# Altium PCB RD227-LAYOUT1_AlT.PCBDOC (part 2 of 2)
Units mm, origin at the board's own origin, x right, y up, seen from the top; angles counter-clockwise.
Board outline 90 x 40 mm, 4 copper layers (TOP, Mid-Layer 1, Mid-Layer 2, BOTTOM), stack 0.711 mm thick; 157 components, 70 nets, 392 pads, 454 vias.
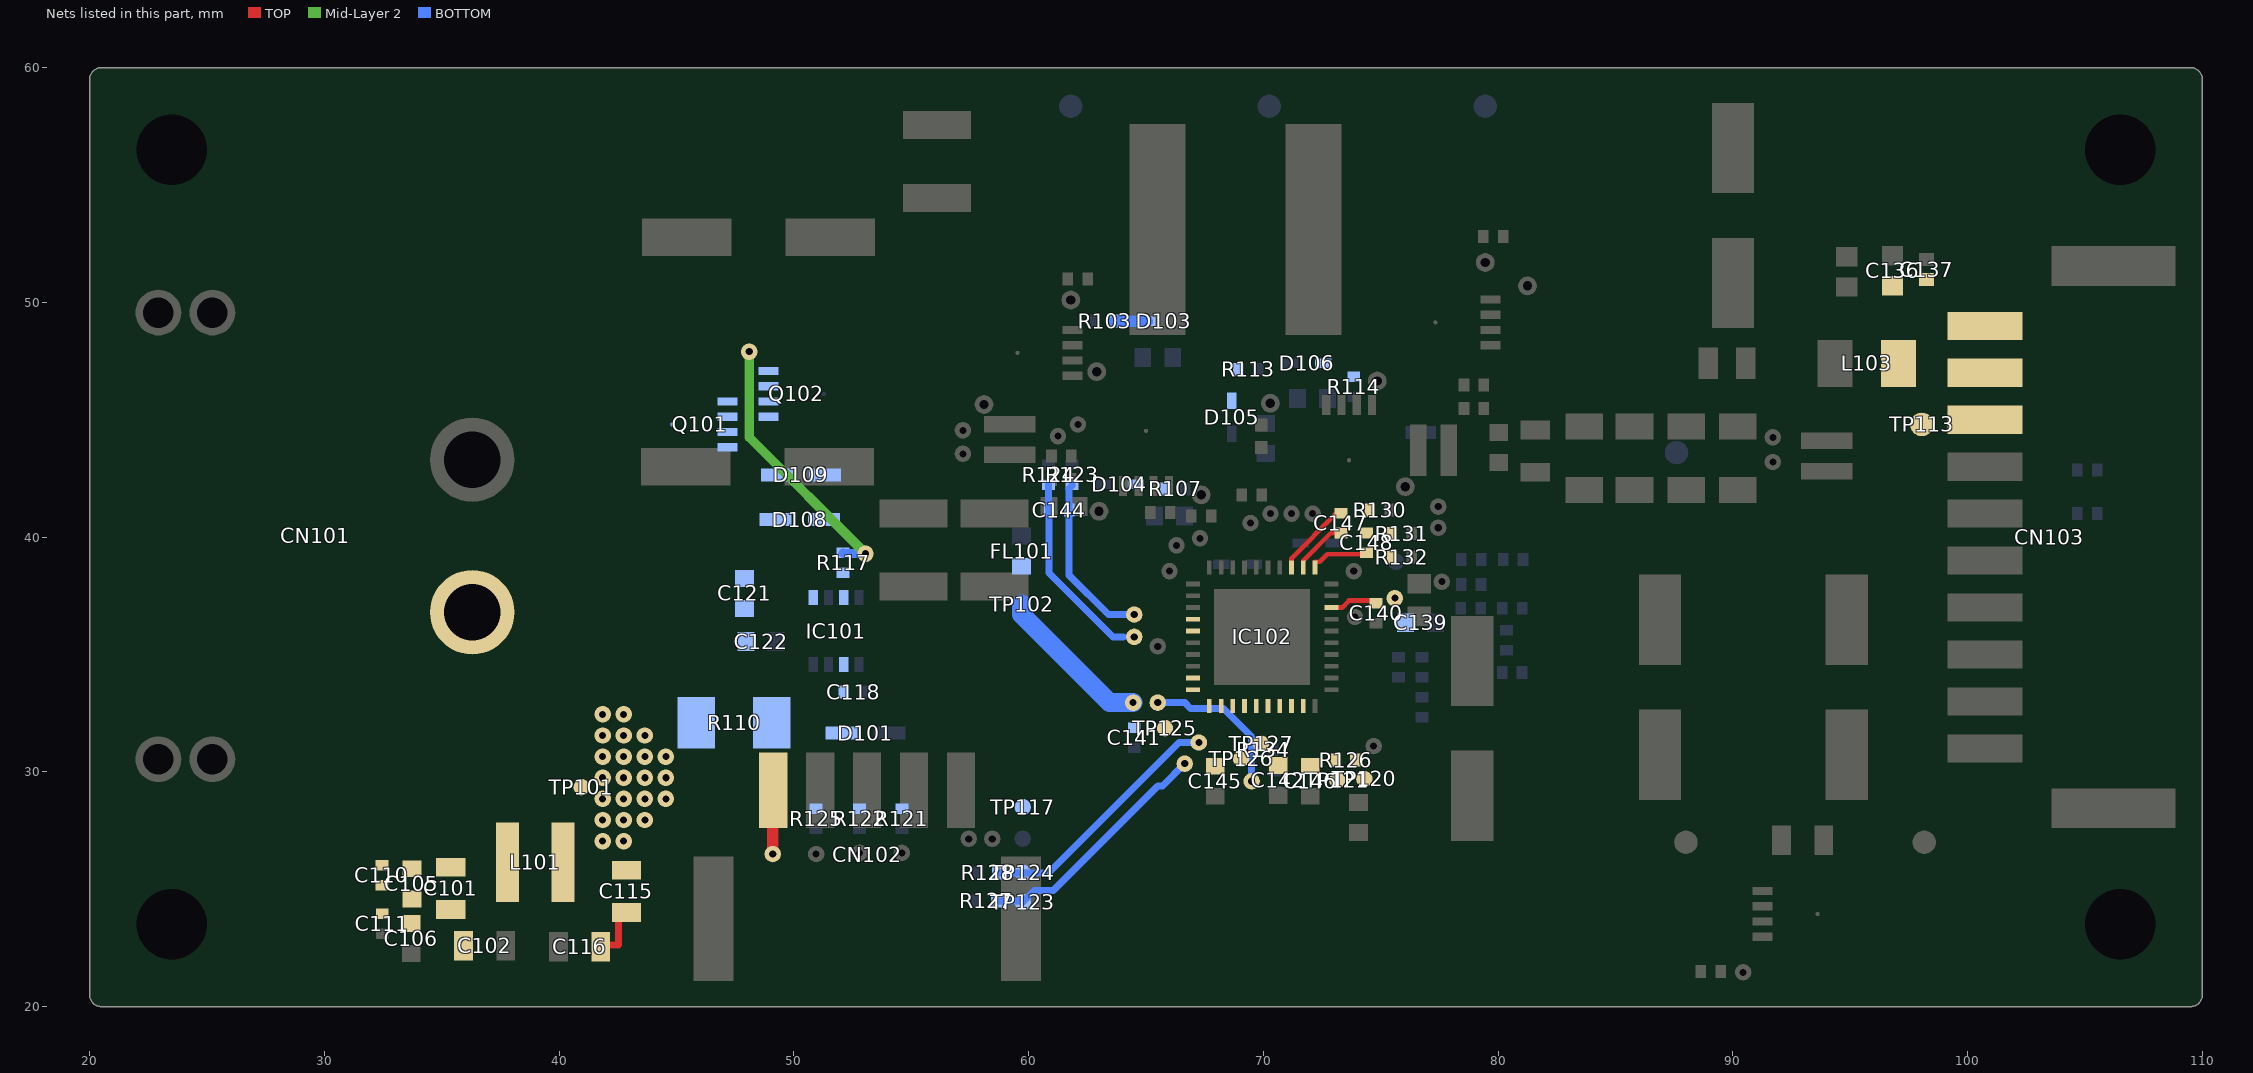
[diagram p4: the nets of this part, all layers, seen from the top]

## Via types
v1: diameter 0.7, hole 0.3, TOP to BOTTOM, 414 vias
v2: diameter 0.8, hole 0.4, TOP to BOTTOM, 40 vias

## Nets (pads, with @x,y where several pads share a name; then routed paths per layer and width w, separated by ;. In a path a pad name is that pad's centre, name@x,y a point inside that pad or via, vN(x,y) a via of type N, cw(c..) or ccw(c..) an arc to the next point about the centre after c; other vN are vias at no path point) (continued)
SIG319: C147.1 C148.2 IC102.32 R131.2 | length 1.9
  TOP w0.2: IC102.32@71.7,38.948 71.7,39 72.875,40.175 C147.1@73.1,40.175
SIG324: C148.1 IC102.31 R132.2 | length 2.5
  TOP w0.2: IC102.31@72.2,38.948 72.398,38.948 72.725,39.275 C148.1@74.575,39.275
SIG328: C147.2 IC102.33 R130.2 | length 3.1
  TOP w0.2: IC102.33@71.2,38.8 71.2,39.1 73.113,41.013 C147.2@73.175,40.95
SIG335: C144.1 IC102.5 pad.@64.5,35.75 R124.1 | length 8.5
  BOTTOM w0.2: 64.05,35.75 pad.@64.5,35.75
  BOTTOM w0.3: R124.1@60.85,42.225 60.85,41.175 C144.1@60.875,41.15 60.875,38.475 63.6,35.75 64.05,35.75
SIG337: C144.2 IC102.4 pad.@64.5,36.7 R123.1 | length 7.4
  BOTTOM w0.3: R123.1@61.85,42.225 61.84,42.235 61.84,42.18 61.725,42.065 C144.2@61.725,41.15 61.725,38.375 63.4,36.7 pad.@64.5,36.7
SIG341: IC102.10 TP125.1
SIG344: IC102.19 R126.1 TP120.1
SIG345: IC102.18 R126.2 TP121.1
SIG346: C145.1 IC102.13
SIG347: C146.1 IC102.17
SIG349: IC102.14 TP126.1
SIG350: IC102.15 TP127.1
SIG369: IC102.11 pad.@66.65,30.35 R127.1 TP123.1 | length 10.4
  BOTTOM w0.3: R127.1@58.675,24.5 59.7,24.5 TP123.1@59.75,24.45 60.25,24.95 61.05,24.95 65.503,29.403 65.703,29.403 pad.@66.65,30.35
SIG370: IC102.12 pad.@67.25,31.25 R128.1 TP124.1 | length 10.9
  BOTTOM w0.3: R128.1@58.675,25.7 TP124.1@59.75,25.7 60.85,25.7 66.4,31.25 pad.@67.25,31.25
SIG422: C118.2 D101.C IC101.6 R110.1
SIG424: D103.A R103.2 | length 1.4
  BOTTOM w0.5: R103.2@63.675,49.2 D103.A@65.05,49.2
SIG425: D104.A R107.2
SIG426: D109.A Q101.1 Q101.2 Q101.3 Q102.1 Q102.2 Q102.3
SIG427: C101.1 C102.2
SIG428: C105.1 C106.2
SIG429: C110.1 C111.2
SIG432: C121.1 C122.2
SIG434: D105.A R113.2
SIG435: D106.A R114.2
SIG439: C115.1 C116.2 | length 2.1
  TOP w0.3: C116.2@41.802,22.63 42.531,22.63 C115.1@42.531,23.955
SIG446: IC101.3 R117.1
SIG449: D108.C D109.C
SIG450: D108.A Q101.4 Q102.4 R117.2 | length 11.6
  Mid-Layer 2 w0.4: v1(48.1,47.9) 48.1,44.25 v1(53.05,39.3)
  BOTTOM w0.4: R117.2@52.1,39.325 52.125,39.3 v1(53.05,39.3) v1@53.075,39.3
VBAT: C139.2 C140.2 FL101.2 IC102.28 TP102.1 | length 9
  TOP w0.2: IC102.28@72.898,37 73.35,37 73.65,37.3 C140.2@74.925,37.3
  BOTTOM w0.3: v1(75.6,37.4) v1@75.646,37.446
  BOTTOM w0.8: TP102.1@59.7,37.15 59.7,36.7 63.45,32.95 v1(64.45,32.95)
VBUS: C136.2 C137.2 CN103.8 CN103.9 CN103.10 L103.2 TP113.1
VDD: C141.2 C142.1 CN102.1 IC102.9 IC102.16 pad.@49.1,26.5 pad.@65.5,32.95 pad.@69.5,29.6 R121.1 R122.1 R125.1 R134.1 TP117.1 | length 9.2
  TOP w0.5: pad.@49.1,26.5 CN102.1@49.1,29.2
  BOTTOM w0.3: pad.@65.5,32.95 66.65,32.95 66.9,32.7 68.3,32.7 69.5,31.5 pad.@69.5,29.6
VIN: C101.2 C105.2 C110.2 CN101.1 L101.1
VIN2: C115.2 C121.2 IC101.1 L101.2 Q101.5 R110.2 TP101.1
  other v1: 41.85,27.05 42.75,27.05 41.85,27.95 42.75,27.95 43.65,27.95 41.85,28.85 42.75,28.85 43.65,28.85 44.55,28.85 41.85,29.75 42.75,29.75 43.65,29.75 44.55,29.75 41.85,30.65 42.75,30.65 43.65,30.65 44.55,30.65 41.85,31.55 42.75,31.55 43.65,31.55 41.85,32.45 42.75,32.45
pads on no net: CAM10. CAM11. CAM12. CAM13. IC101.4 IC101.7 IC101.8

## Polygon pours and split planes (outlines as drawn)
DL1_Q on TOP "TOP1" (solid, pour order 71): 20 vertices, not listed, extent 65.8,40.85 67.3,42.55
DH1 on TOP "TOP2" (solid, pour order 72): 67.65,38.4 cw(c67.65,38.45) 67.6,38.45 67.6,39.2 66.965,39.835 cw(c67,39.871) 66.95,39.871 66.95,40.079 cw(c67,40.079) 66.965,40.115 67.135,40.285 cw(c67.171,40.25) 67.171,40.3 67.429,40.3 cw(c67.429,40.25) 67.465,40.285 67.785,39.965 cw(c67.75,39.929) 67.8,39.929 67.8,38.45 cw(c67.75,38.45) 67.75,38.4
SIG319 on TOP "TOP3" (solid, pour order 73): 75.271,39.85 cw(c75.271,39.9) 75.235,39.865 75.15,39.95 73.1,39.95 cw(c73.1,40) 73.05,40 73.05,40.35 cw(c73.1,40.35) 73.1,40.4 75.55,40.4 cw(c75.55,40.35) 75.6,40.35 75.6,39.9 cw(c75.55,39.9) 75.55,39.85
SIG318 on TOP "TOP4" (solid, pour order 74): 72.75,37.9 cw(c72.75,37.95) 72.7,37.95 72.7,38.05 cw(c72.75,38.05) 72.75,38.1 73,38.1 73.435,38.535 cw(c73.471,38.5) 73.471,38.55 74,38.55 cw(c74,38.5) 74.05,38.5 74.05,38.25 cw(c74,38.25) 74,38.2 73.5,38.2 73.215,37.915 cw(c73.179,37.95) 73.179,37.9
SIG310 on TOP "TOP5" (solid, pour order 75): 73.15,36.4 cw(c73.15,36.45) 73.1,36.45 73.1,36.55 cw(c73.15,36.55) 73.15,36.6 73.4,36.6 73.685,36.885 cw(c73.721,36.85) 73.721,36.9 73.9,36.9 cw(c73.9,36.85) 73.95,36.85 73.95,36.45 cw(c73.9,36.45) 73.9,36.4
SIG324 on TOP "TOP6" (solid, pour order 76): 75.071,38.9 cw(c75.071,38.95) 75.035,38.915 74.85,39.1 74.2,39.1 cw(c74.2,39.15) 74.15,39.15 74.15,39.5 cw(c74.2,39.5) 74.2,39.55 75.079,39.55 cw(c75.079,39.5) 75.115,39.535 75.25,39.4 75.45,39.4 cw(c75.45,39.35) 75.5,39.35 75.5,38.95 cw(c75.45,38.95) 75.45,38.9
SIG328 on TOP "TOP7" (solid, pour order 77): 73,40.8 cw(c73,40.85) 72.95,40.85 72.95,41.2 cw(c73,41.2) 73,41.25 73.7,41.25 73.835,41.385 cw(c73.871,41.35) 73.871,41.4 74.6,41.4 cw(c74.6,41.35) 74.65,41.35 74.65,40.95 cw(c74.6,40.95) 74.6,40.9 74.2,40.9 74.115,40.815 cw(c74.079,40.85) 74.079,40.8
CSN2 on TOP "TOP8" (solid, pour order 78): 76.15,38.9 cw(c76.15,38.95) 76.1,38.95 76.1,39.4 cw(c76.15,39.4) 76.15,39.45 76.65,39.45 77.1,39.9 77.1,40.45 cw(c77.15,40.45) 77.15,40.5 77.75,40.5 cw(c77.75,40.45) 77.8,40.45 77.8,40.021 cw(c77.75,40.021) 77.785,39.985 76.715,38.915 cw(c76.679,38.95) 76.679,38.9
DH2 on TOP "TOP9" (solid, pour order 79): 69.15,38.45 cw(c69.15,38.5) 69.1,38.5 69.1,40.579 cw(c69.15,40.579) 69.115,40.615 69.235,40.735 cw(c69.271,40.7) 69.271,40.75 69.629,40.75 cw(c69.629,40.7) 69.665,40.735 69.785,40.615 cw(c69.75,40.579) 69.8,40.579 69.8,40.371 cw(c69.75,40.371) 69.785,40.335 69.3,39.85 69.3,38.5 cw(c69.25,38.5) 69.25,38.45
DL2 on TOP "TOP10" (solid, pour order 80): 70.15,38.4 cw(c70.15,38.45) 70.1,38.45 70.1,39.529 cw(c70.15,39.529) 70.115,39.565 70.85,40.3 70.85,40.95 cw(c70.9,40.95) 70.9,41 71.5,41 cw(c71.5,40.95) 71.55,40.95 71.55,40.521 cw(c71.5,40.521) 71.535,40.485 70.3,39.25 70.3,38.45 cw(c70.25,38.45) 70.25,38.4
BST1 on TOP "TOP11" (solid, pour order 81): 37 vertices, not listed, extent 65.95,37.9 67.2,40.85
DL1 on TOP "TOP12" (solid, pour order 82): 66.521,37.4 cw(c66.521,37.45) 66.485,37.415 65.665,38.235 cw(c65.7,38.271) 65.65,38.271 65.65,38.5 cw(c65.7,38.5) 65.7,38.55 66.3,38.55 cw(c66.3,38.5) 66.35,38.5 66.35,37.95 66.7,37.6 67.2,37.6 cw(c67.2,37.55) 67.25,37.55 67.25,37.45 cw(c67.2,37.45) 67.2,37.4
SIG337 on TOP "TOP13" (solid, pour order 83): 64.55,36.4 cw(c64.55,36.45) 64.5,36.45 64.5,36.8 cw(c64.55,36.8) 64.55,36.85 64.729,36.85 cw(c64.729,36.8) 64.765,36.835 65,36.6 67.25,36.6 cw(c67.25,36.55) 67.3,36.55 67.3,36.45 cw(c67.25,36.45) 67.25,36.4
SIG335 on TOP "TOP14" (solid, pour order 84): 64.25,35.7 cw(c64.25,35.75) 64.2,35.75 64.2,35.979 cw(c64.25,35.979) 64.215,36.015 64.285,36.085 cw(c64.321,36.05) 64.321,36.1 67.25,36.1 cw(c67.25,36.05) 67.3,36.05 67.3,35.95 cw(c67.25,35.95) 67.25,35.9 65,35.9 64.815,35.715 cw(c64.779,35.75) 64.779,35.7
HVEN on TOP "TOP15" (solid, pour order 85): 65.45,35.05 cw(c65.45,35.1) 65.4,35.1 65.4,35.65 cw(c65.45,35.65) 65.45,35.7 65.779,35.7 cw(c65.779,35.65) 65.815,35.685 65.9,35.6 67.25,35.6 cw(c67.25,35.55) 67.3,35.55 67.3,35.45 cw(c67.25,35.45) 67.25,35.4 66.1,35.4 65.765,35.065 cw(c65.729,35.1) 65.729,35.05
GDRV on TOP "TOP16" (solid, pour order 86): 65.55,33.65 cw(c65.55,33.7) 65.5,33.7 65.5,34.3 cw(c65.55,34.3) 65.55,34.35 66.309,34.35 66.529,34.571 cw(c66.6,34.5) 66.6,34.6 67.002,34.6 cw(c67.002,34.5) 67.002,34.4 66.641,34.4 66.527,34.286 cw(c66.479,34.3) 66.515,34.265 66.514,34.264 65.915,33.665 cw(c65.879,33.7) 65.879,33.65
VDD on TOP "TOP17" (solid, pour order 87): 20 vertices, not listed, extent 65.3,32.6 67.102,34.1
HVCC1 on TOP "TOP18" (solid, pour order 88): 18 vertices, not listed, extent 72.798,34.784 74.8,35.6
HVCC2 on TOP "TOP19" (solid, pour order 89): 74.55,34.1 cw(c74.55,34.2) 74.479,34.129 73.709,34.9 72.898,34.9 cw(c72.898,35) 72.898,35.1 73.75,35.1 cw(c73.75,35) 73.821,35.071 74.342,34.549 cw(c74.35,34.5) 74.35,34.55 74.75,34.55 cw(c74.75,34.5) 74.8,34.5 74.8,34.3 cw(c74.8,34.2) 74.8,34.1
HVDM on TOP "TOP20" (solid, pour order 90): 73.441,32.75 cw(c73.441,32.85) 73.371,32.779 73.329,32.821 cw(c73.4,32.891) 73.3,32.891 73.3,33.259 73.159,33.4 72.898,33.4 cw(c72.898,33.5) 72.898,33.6 73.2,33.6 cw(c73.2,33.5) 73.271,33.571 73.92,32.921 73.921,32.921 cw(c73.85,32.85) 73.95,32.85 cw(c73.85,32.85) 73.85,32.75
HVDP on TOP "TOP21" (solid, pour order 91): 74.45,31.95 cw(c74.45,32.05) 74.35,32.05 74.35,32.959 73.409,33.9 72.898,33.9 cw(c72.898,34) 72.898,34.1 73.45,34.1 cw(c73.45,34) 73.521,34.071 74.827,32.765 cw(c74.756,32.694) 74.856,32.694 74.856,32.452 74.967,32.079 cw(c74.871,32.05) 74.871,31.95
SIG369 on TOP "TOP22" (solid, pour order 92): 19 vertices, not listed, extent 66.311,30.25 67.8,33.152
SIG370 on TOP "TOP23" (solid, pour order 93): 67.129,31.15 cw(c67.129,31.25) 67.029,31.25 67.029,31.409 cw(c67.129,31.409) 67.059,31.479 67.224,31.644 cw(c67.294,31.574) 67.271,31.671 68.1,32.5 68.1,33.052 cw(c68.2,33.052) 68.3,33.052 68.3,32.391 cw(c68.2,32.391) 68.271,32.321 67.6,31.65 67.6,31.25 cw(c67.5,31.25) 67.5,31.15
SIG346 on TOP "TOP24" (solid, pour order 94): 67.65,29.9 cw(c67.65,30) 67.55,30 67.55,30.609 cw(c67.65,30.609) 67.579,30.679 67.85,30.95 67.85,31.388 cw(c68,31.388) 67.894,31.494 68.6,32.2 68.6,33.052 cw(c68.7,33.052) 68.8,33.052 68.8,31.591 cw(c68.7,31.591) 68.771,31.521 68.35,31.1 68.35,30 cw(c68.25,30) 68.25,29.9
SIG349 on TOP "TOP25" (solid, pour order 95): 68.8,30.45 cw(c68.8,30.55) 68.7,30.55 68.7,31.009 cw(c68.8,31.009) 68.729,31.079 69.1,31.45 69.1,33.052 cw(c69.2,33.052) 69.3,33.052 69.3,30.9 69.371,30.829 cw(c69.3,30.759) 69.4,30.759 69.4,30.55 cw(c69.3,30.55) 69.3,30.45
SIG347 on TOP "TOP26" (solid, pour order 96): 71.7,29.9 cw(c71.7,30) 71.6,30 71.6,31.1 70.629,32.071 cw(c70.7,32.141) 70.6,32.141 70.6,33.052 cw(c70.7,33.052) 70.8,33.052 70.8,32.35 72.371,30.779 cw(c72.3,30.709) 72.4,30.709 72.4,30 cw(c72.3,30) 72.3,29.9
ALERT on TOP "TOP27" (solid, pour order 97): 21 vertices, not listed, extent 72.1,31 74.8,32.841
LX2 on TOP "TOP28" (solid, pour order 98): 24 vertices, not listed, extent 68.6,38.4 70.2,43.95
CSP1 on TOP "TOP29" (solid, pour order 99): 60.7,44 cw(c60.7,44.05) 60.65,44.05 60.65,44.179 cw(c60.7,44.179) 60.665,44.215 61.085,44.635 cw(c61.121,44.6) 61.121,44.65 61.25,44.65 cw(c61.25,44.6) 61.3,44.6 61.3,44.05 cw(c61.25,44.05) 61.25,44
CSN1 on TOP "TOP30" (solid, pour order 100): 61.821,44.65 cw(c61.821,44.7) 61.785,44.665 61.515,44.935 cw(c61.55,44.971) 61.5,44.971 61.5,45.05 cw(c61.55,45.05) 61.55,45.1 62.15,45.1 cw(c62.15,45.05) 62.2,45.05 62.2,44.7 cw(c62.15,44.7) 62.15,44.65
GND_A on TOP "TOP31" (solid, pour order 101): 46,21 cw(c46,21.15) 45.85,21.15 45.85,24.65 cw(c46,24.65) 46,24.8 55.45,24.8 56.55,25.9 56.55,30.85 cw(c56.7,30.85) 56.7,31 58.838,31 cw(c58.838,30.85) 58.944,30.956 60.506,29.394 cw(c60.4,29.288) 60.55,29.288 60.55,21.15 cw(c60.4,21.15) 60.4,21
VIN on TOP "TOP32" (solid, pour order 102): 41 vertices, not listed, extent 32.144,24.463 38.304,38.65
SIG341 on TOP "TOP33" (solid, pour order 103): 24 vertices, not listed, extent 65.65,31.75 67.102,33.6
VIN2 on TOP "TOP34" (solid, pour order 104): 26 vertices, not listed, extent 39.666,24.507 44.9,33.454
SIG427 on TOP "TOP35" (solid, pour order 105): 35.6,22 cw(c35.6,22.05) 35.55,22.05 35.55,22.4 34.815,23.135 cw(c34.85,23.171) 34.8,23.171 34.8,24.1 cw(c34.85,24.1) 34.85,24.15 35.95,24.15 cw(c35.95,24.1) 36,24.1 36,23.65 36.285,23.365 cw(c36.25,23.329) 36.3,23.329 36.3,22.05 cw(c36.25,22.05) 36.25,22
SIG428 on TOP "TOP36" (solid, pour order 106): 33.35,23.45 cw(c33.35,23.5) 33.3,23.5 33.3,24.55 cw(c33.35,24.55) 33.35,24.6 34.05,24.6 cw(c34.05,24.55) 34.1,24.55 34.1,23.5 cw(c34.05,23.5) 34.05,23.45
SIG429 on TOP "TOP37" (solid, pour order 107): 32.25,23.85 cw(c32.25,23.9) 32.2,23.9 32.2,25.2 cw(c32.25,25.2) 32.25,25.25 32.65,25.25 cw(c32.65,25.2) 32.7,25.2 32.7,23.9 cw(c32.65,23.9) 32.65,23.85
GND_A on TOP "TOP38" (solid, pour order 108): 108.05,37.1 cw(c108.05,37.15) 108,37.15 108,43.8 cw(c108.05,43.8) 108.05,43.85 108.95,43.85 cw(c108.95,43.8) 109,43.8 109,37.15 cw(c108.95,37.15) 108.95,37.1
SIG350 on TOP "TOP39" (solid, pour order 109): 69.65,31.2 cw(c69.65,31.3) 69.55,31.3 69.55,31.409 cw(c69.65,31.409) 69.579,31.479 69.6,31.5 69.6,33.052 cw(c69.7,33.052) 69.8,33.052 69.8,31.8 70.146,31.454 cw(c70.075,31.383) 70.175,31.383 70.175,31.316 cw(c70.075,31.316) 70.146,31.245 70.13,31.229 cw(c70.06,31.3) 70.06,31.2
BST2 on TOP "TOP40" (solid, pour order 110): 24 vertices, not listed, extent 69.6,38.8 70.65,41.95
ADDR on TOP "TOP41" (solid, pour order 111): 70.6,39.2 cw(c70.7,39.2) 70.629,39.271 71.754,40.396 71.754,40.914 cw(c71.854,40.914) 71.854,41.014 72.327,41.014 cw(c72.327,40.914) 72.427,40.914 72.427,40.869 cw(c72.327,40.869) 72.398,40.798 72.2,40.6 cw(c72.1,40.6) 72.171,40.529 70.8,39.159 70.8,38.948 cw(c70.7,38.948) 70.6,38.948
GDRV on TOP "TOP42" (solid, pour order 112): 89.3,21.1 cw(c89.3,21.15) 89.25,21.15 89.25,21.75 cw(c89.3,21.75) 89.3,21.8 90.2,21.8 90.837,22.437 90.837,23.05 cw(c90.887,23.05) 90.887,23.1 91.65,23.1 cw(c91.65,23.05) 91.7,23.05 91.7,21.721 cw(c91.65,21.721) 91.685,21.685 91.115,21.115 cw(c91.079,21.15) 91.079,21.1
SIG345 on TOP "TOP43" (solid, pour order 113): 20 vertices, not listed, extent 71.1,29.65 73.5,33.152
SIG344 on TOP "TOP44" (solid, pour order 114): 27 vertices, not listed, extent 71.6,29.7 74.55,33.152
SHLD_SNS on TOP "TOP45" (solid, pour order 115): 54 vertices, not listed, extent 92.142,20.987 108.927,52.721
CSP1 on TOP "TOP46" (solid, pour order 116): 29 vertices, not listed, extent 49.65,40.402 61.2,55.1
CSP2 on TOP "TOP47" (solid, pour order 117): 76.779,42.398 cw(c76.779,42.448) 76.729,42.448 76.729,42.537 cw(c76.779,42.537) 76.779,42.587 76.915,42.587 cw(c76.915,42.537) 76.965,42.537 76.965,42.448 cw(c76.915,42.448) 76.915,42.398
GND_A on TOP "TOP48" (solid, pour order 118): 76 vertices, not listed, extent 67.55,28.337 77.131,37
BIAS on TOP "TOP49" (solid, pour order 119): 22 vertices, not listed, extent 74.55,37.612 77.967,38.5
OUT on TOP "TOP50" (solid, pour order 120): 76.15,39.95 cw(c76.15,40) 76.1,40 76.1,40.404 cw(c76.15,40.404) 76.115,40.439 77.261,41.585 cw(c77.296,41.55) 77.296,41.6 77.6,41.6 cw(c77.6,41.55) 77.65,41.55 77.65,41 cw(c77.6,41) 77.6,40.95 77.175,40.95 76.55,40.325 76.55,40 cw(c76.5,40) 76.5,39.95
VBAT on TOP "TOP51" (solid, pour order 121): 74.519,37.052 cw(c74.519,37.102) 74.484,37.066 74.365,37.185 cw(c74.4,37.221) 74.35,37.221 74.35,37.35 cw(c74.4,37.35) 74.4,37.4 75.069,37.4 75.297,37.628 cw(c75.332,37.593) 75.332,37.643 75.85,37.643 cw(c75.85,37.593) 75.9,37.593 75.9,37.246 cw(c75.85,37.246) 75.885,37.211 75.741,37.066 cw(c75.706,37.102) 75.706,37.052
GND_P on TOP "TOP52" (solid, pour order 122): 48 vertices, not listed, extent 79.163,44.118 99.05,59
GND_P on TOP "TOP53" (solid, pour order 123): 214 vertices, not listed, extent 21.05,21 95.65,58.93
VBUS on TOP "TOP54" (solid, pour order 124): 20 vertices, not listed, extent 96.35,44.221 102.3,51
CSN2 on TOP "TOP55" (solid, pour order 125): 21 vertices, not listed, extent 89.1,43.8 95.3,52.7
VDD on TOP "TOP56" (solid, pour order 126): 24 vertices, not listed, extent 69.273,29.373 71,33.152
DH2_Q on TOP "TOP57" (solid, pour order 127): 18 vertices, not listed, extent 69.65,44.55 72.846,46.047
LX1 on TOP "TOP58" (solid, pour order 128): 22 vertices, not listed, extent 67.385,38.4 68.3,43.15
DH1_Q on TOP "TOP59" (solid, pour order 129): 61.5,48.7 cw(c61.5,48.75) 61.45,48.75 61.45,51.05 cw(c61.5,51.05) 61.5,51.1 61.85,51.1 cw(c61.85,51.05) 61.9,51.05 61.9,50.6 62.285,50.215 cw(c62.25,50.179) 62.3,50.179 62.3,48.75 cw(c62.25,48.75) 62.25,48.7
DL2_Q on TOP "TOP60" (solid, pour order 130): 18 vertices, not listed, extent 79.127,50.067 80.097,52.774
CSP2 on TOP "TOP61" (solid, pour order 131): 17 vertices, not listed, extent 71.5,41.75 76.943,45.055
OUT on TOP "TOP62" (solid, pour order 132): 49 vertices, not listed, extent 77.55,32.75 96.1,46.75
LX2 on TOP "TOP63" (solid, pour order 133): 28 vertices, not listed, extent 70.9,45.2 78.749,58.9
LX1 on TOP "TOP64" (solid, pour order 134): 34 vertices, not listed, extent 61.464,43.1 67.15,58.95
CSN1 on TOP "TOP65" (solid, pour order 135): 17 vertices, not listed, extent 57.65,44.6 61,50
LX2 on Mid-Layer 1 "MID166" (solid, pour order 58): 76.4,46.95 cw(c76.4,47.1) 76.25,47.1 76.25,49.422 cw(c76.4,49.422) 76.4,49.572 78.1,49.572 cw(c78.1,49.422) 78.25,49.422 78.25,47.1 cw(c78.1,47.1) 78.1,46.95
CSP2 on Mid-Layer 1 "MID167" (solid, pour order 59): 71.708,42.684 cw(c71.708,42.834) 71.558,42.834 71.558,44.552 cw(c71.708,44.552) 71.708,44.702 73.943,44.702 cw(c73.943,44.552) 74.093,44.552 74.093,42.834 cw(c73.943,42.834) 73.943,42.684
SHLD_SNS on Mid-Layer 1 "MID168" (solid, pour order 60): 92.295,22.65 cw(c92.295,22.75) 92.195,22.75 92.195,24.668 cw(c92.295,24.668) 92.295,24.768 94.144,24.768 cw(c94.144,24.668) 94.244,24.668 94.244,22.75 cw(c94.144,22.75) 94.144,22.65
SHLD_SNS on Mid-Layer 1 "MID170" (solid, pour order 62): 18 vertices, not listed, extent 92.2,20.987 106.598,33.739
VBAT on Mid-Layer 1 "MID171" (solid, pour order 63): 26 vertices, not listed, extent 64.05,31.855 75.879,37.523
CSP2 on Mid-Layer 1 "MID172" (solid, pour order 64): 23 vertices, not listed, extent 71.5,41.75 76.498,45.055
CSP1 on Mid-Layer 1 "MID173" (solid, pour order 65): 54.101,44.15 cw(c54.101,44.2) 54.066,44.165 52.909,45.321 cw(c52.944,45.357) 52.894,45.357 52.894,50.35 cw(c52.944,50.35) 52.944,50.4 57.2,50.4 cw(c57.2,50.35) 57.25,50.35 57.25,45.971 cw(c57.2,45.971) 57.235,45.935 55.465,44.165 cw(c55.429,44.2) 55.429,44.15
CSN1 on Mid-Layer 1 "MID174" (solid, pour order 66): 58.013,45.204 cw(c58.013,45.254) 57.977,45.219 57.65,45.547 cw(c57.685,45.582) 57.635,45.582 57.635,49.465 cw(c57.685,49.465) 57.65,49.5 58.135,49.985 cw(c58.171,49.95) 58.171,50 60.9,50 cw(c60.9,49.85) 61.05,49.85 61.05,45.859 cw(c60.9,45.859) 61.006,45.753 60.472,45.219 cw(c60.437,45.254) 60.437,45.204
LX1 on Mid-Layer 1 "MID175" (solid, pour order 67): 21 vertices, not listed, extent 62.85,43.088 67.15,46.45
LX2 on Mid-Layer 1 "MID176" (solid, pour order 68): 75.771,46.95 cw(c75.771,47) 75.735,46.965 75.418,47.282 cw(c75.453,47.318) 75.403,47.318 75.403,51.15 cw(c75.553,51.15) 75.553,51.3 78.681,51.3 cw(c78.681,51.15) 78.831,51.15 78.831,47.1 cw(c78.681,47.1) 78.681,46.95
GND_A on Mid-Layer 1 "MID178" (solid, pour order 70): 29 vertices, not listed, extent 68.35,28.35 108.95,44.863
VIN2 on Mid-Layer 1 "MID169" (solid, pour order 61): 41.5,26.65 cw(c41.5,26.7) 41.45,26.7 41.45,32.85 cw(c41.5,32.85) 41.5,32.9 43.129,32.9 cw(c43.129,32.85) 43.165,32.885 44.935,31.115 cw(c44.9,31.079) 44.95,31.079 44.95,28.321 cw(c44.9,28.321) 44.935,28.285 43.315,26.665 cw(c43.279,26.7) 43.279,26.65
GND_P on Mid-Layer 1 "MID177" (solid, pour order 69): 161 vertices, not listed, extent 20.986,21 101.75,59
GND_A on Mid-Layer 2 "MID291" (solid, pour order 57): 44 vertices, not listed, extent 68.35,28.2 108.9,44.863
GND_P on Mid-Layer 2 "MID290" (solid, pour order 56): 231 vertices, not listed, extent 20.95,21.05 101.9,58.864
CSP2 on Mid-Layer 2 "MID280" (solid, pour order 46): 71.708,42.695 cw(c71.708,42.845) 71.558,42.845 71.558,44.531 cw(c71.708,44.531) 71.708,44.681 73.943,44.681 cw(c73.943,44.531) 74.093,44.531 74.093,42.845 cw(c73.943,42.845) 73.943,42.695
GND_P on Mid-Layer 2 "MID282" (solid, pour order 48): 17 vertices, not listed, extent 79.9,28.2 93.7,29.45
SHLD_SNS on Mid-Layer 2 "MID283" (solid, pour order 49): 18 vertices, not listed, extent 92.2,20.987 106.692,33.954
GND_P on Mid-Layer 2 "MID284" (solid, pour order 50): 68,33.65 cw(c68,33.8) 67.85,33.8 67.85,37.7 cw(c68,37.7) 68,37.85 71.9,37.85 cw(c71.9,37.7) 72.05,37.7 72.05,33.8 cw(c71.9,33.8) 71.9,33.65
CSP2 on Mid-Layer 2 "MID285" (solid, pour order 51): 18 vertices, not listed, extent 71.5,41.75 76.493,45.055
CSP1 on Mid-Layer 2 "MID286" (solid, pour order 52): 54.11,44.15 cw(c54.11,44.2) 54.075,44.165 52.964,45.275 cw(c53,45.311) 52.95,45.311 52.95,50.35 cw(c53,50.35) 53,50.4 57.2,50.4 cw(c57.2,50.35) 57.25,50.35 57.25,45.971 cw(c57.2,45.971) 57.235,45.935 55.465,44.165 cw(c55.429,44.2) 55.429,44.15
LX1 on Mid-Layer 2 "MID288" (solid, pour order 54): 17 vertices, not listed, extent 62.85,43.035 67.15,46.45
CSN1 on Mid-Layer 2 "MID289" (solid, pour order 55): 58.013,45.204 cw(c58.013,45.254) 57.977,45.219 57.665,45.532 cw(c57.7,45.567) 57.65,45.567 57.65,49.55 cw(c57.7,49.55) 57.665,49.585 58.065,49.985 cw(c58.1,49.95) 58.1,50 60.9,50 cw(c60.9,49.85) 61.05,49.85 61.05,45.859 cw(c60.9,45.859) 61.006,45.753 60.472,45.219 cw(c60.437,45.254) 60.437,45.204
VIN2 on Mid-Layer 2 "MID281" (solid, pour order 47): 41.5,26.65 cw(c41.5,26.7) 41.45,26.7 41.45,32.85 cw(c41.5,32.85) 41.5,32.9 43.129,32.9 cw(c43.129,32.85) 43.165,32.885 44.935,31.115 cw(c44.9,31.079) 44.95,31.079 44.95,28.321 cw(c44.9,28.321) 44.935,28.285 43.315,26.665 cw(c43.279,26.7) 43.279,26.65
LX2 on Mid-Layer 2 "MID279" (solid, pour order 45): 76.4,46.95 cw(c76.4,47.1) 76.25,47.1 76.25,49.422 cw(c76.4,49.422) 76.4,49.572 78.1,49.572 cw(c78.1,49.422) 78.25,49.422 78.25,47.1 cw(c78.1,47.1) 78.1,46.95
LX2 on Mid-Layer 2 "MID287" (solid, pour order 53): 75.861,46.95 cw(c75.861,47) 75.825,46.965 75.418,47.372 cw(c75.453,47.408) 75.403,47.408 75.403,51.15 cw(c75.553,51.15) 75.553,51.3 78.681,51.3 cw(c78.681,51.15) 78.831,51.15 78.831,47.1 cw(c78.681,47.1) 78.681,46.95
BST1 on BOTTOM "BOTTOM92" (solid, pour order 2): 17 vertices, not listed, extent 66.3,38.65 68.25,39.9
BST2 on BOTTOM "BOTTOM93" (solid, pour order 3): 18 vertices, not listed, extent 69.95,39.55 71.85,41
ADDR on BOTTOM "BOTTOM94" (solid, pour order 4): 40 vertices, not listed, extent 72.008,39.4 79.328,41.342
ADDR on BOTTOM "BOTTOM95" (solid, pour order 5): 79.2,38.8 cw(c79.2,38.95) 79.05,38.95 79.05,39.472 cw(c79.194,39.516) 79.322,39.593 79.615,39.3 80.3,39.3 cw(c80.3,39.15) 80.45,39.15 80.45,38.95 cw(c80.3,38.95) 80.3,38.8
SIG317 on BOTTOM "BOTTOM96" (solid, pour order 6): 22 vertices, not listed, extent 78.964,34.95 80.454,36.25
VDD on BOTTOM "BOTTOM97" (solid, pour order 7): 41 vertices, not listed, extent 48.75,26.255 65.85,32.95
GND_P on BOTTOM "BOTTOM98" (solid, pour order 8): 48.242,21 cw(c48.242,21.15) 48.092,21.15 48.092,22.15 cw(c48.242,22.15) 48.242,22.3 64.6,22.3 cw(c64.6,22.15) 64.75,22.15 64.75,21.15 cw(c64.6,21.15) 64.6,21
SIG432 on BOTTOM "BOTTOM99" (solid, pour order 9): 47.65,35.15 cw(c47.65,35.2) 47.6,35.2 47.6,36.2 47.515,36.285 cw(c47.55,36.321) 47.5,36.321 47.5,36.9 cw(c47.55,36.9) 47.55,36.95 48.25,36.95 cw(c48.25,36.9) 48.3,36.9 48.3,35.2 cw(c48.25,35.2) 48.25,35.15
SIG422 on BOTTOM "BOTTOM100" (solid, pour order 10): 22 vertices, not listed, extent 48.95,31 52.75,34.65
GND_A on BOTTOM "BOTTOM101" (solid, pour order 11): 29 vertices, not listed, extent 105.526,36.396 108.9,44.272
DL1_Q on BOTTOM "BOTTOM102" (solid, pour order 12): 21 vertices, not listed, extent 66.3,40.55 67.6,42.32
SIG425 on BOTTOM "BOTTOM103" (solid, pour order 13): 65.281,41.78 cw(c65.281,41.83) 65.245,41.795 64.98,42.06 64.27,42.06 cw(c64.27,42.11) 64.22,42.11 64.22,42.41 cw(c64.27,42.41) 64.27,42.46 65.379,42.46 cw(c65.379,42.41) 65.415,42.445 65.54,42.32 65.87,42.32 cw(c65.87,42.27) 65.92,42.27 65.92,41.83 cw(c65.87,41.83) 65.87,41.78
DL1 on BOTTOM "BOTTOM104" (solid, pour order 14): 30 vertices, not listed, extent 62.82,38.18 66.18,42.46
CSP1 on BOTTOM "BOTTOM105" (solid, pour order 15): 59.7,39.74 cw(c59.7,40.14) 59.3,40.14 59.3,40.884 56.917,43.267 cw(c57.2,43.55) 57.483,43.833 59.983,41.333 cw(c59.7,41.05) 60.1,41.05 60.1,40.14 cw(c59.7,40.14) 59.7,39.74
VBAT on BOTTOM "BOTTOM106" (solid, pour order 16): 59.3,38.62 cw(c59.7,38.62) 59.7,39.02 cw(c59.7,38.62) 60.1,38.62 60.1,37.15 cw(c59.7,37.15) 59.3,37.15
SHLD_SNS on BOTTOM "BOTTOM107" (solid, pour order 17): 18 vertices, not listed, extent 92.2,20.987 106.682,33.886
GND_A on BOTTOM "BOTTOM108" (solid, pour order 18): 54 vertices, not listed, extent 72.15,28.25 82.65,39.318
VBAT on BOTTOM "BOTTOM109" (solid, pour order 19): 75.788,36.078 cw(c75.788,36.128) 75.738,36.128 75.738,36.577 cw(c75.738,36.627) 75.703,36.591 75.279,37.015 cw(c75.314,37.05) 75.264,37.05 75.264,37.7 cw(c75.314,37.7) 75.314,37.75 75.761,37.75 cw(c75.761,37.7) 75.797,37.735 76.423,37.109 cw(c76.388,37.073) 76.438,37.073 76.438,36.128 cw(c76.388,36.128) 76.388,36.078
DH2_Q on BOTTOM "BOTTOM110" (solid, pour order 20): 19 vertices, not listed, extent 69.557,44.518 70.64,47.278
SIG435 on BOTTOM "BOTTOM111" (solid, pour order 21): 73.647,46.625 cw(c73.647,46.675) 73.597,46.675 73.597,46.83 73.218,47.21 72.253,47.21 cw(c72.253,47.26) 72.203,47.26 72.203,47.562 cw(c72.253,47.562) 72.253,47.612 73.604,47.612 cw(c73.604,47.562) 73.639,47.597 74.131,47.106 cw(c74.095,47.07) 74.145,47.07 74.145,46.675 cw(c74.095,46.675) 74.095,46.625
CSN2 on BOTTOM "BOTTOM112" (solid, pour order 22): 17 vertices, not listed, extent 77.439,40.057 78.394,40.845
GND_P on BOTTOM "BOTTOM113" (solid, pour order 23): 161 vertices, not listed, extent 20.95,21 102.5,58.95
GND_A on BOTTOM "BOTTOM114" (solid, pour order 24): 40 vertices, not listed, extent 56.8,26.75 70.791,32.25
GND_P on BOTTOM "BOTTOM115" (solid, pour order 25): 29 vertices, not listed, extent 49,31.2 58.45,38.2
CSP2 on BOTTOM "BOTTOM116" (solid, pour order 26): 18 vertices, not listed, extent 71.5,41.75 76.493,45.055
GND_P on BOTTOM "BOTTOM117" (solid, pour order 27): 20 vertices, not listed, extent 62.6,33.7 68.85,41.5
GND_P on BOTTOM "BOTTOM118" (solid, pour order 28): 68,33.65 cw(c68,33.8) 67.85,33.8 67.85,37.7 cw(c68,37.7) 68,37.85 71.9,37.85 cw(c71.9,37.7) 72.05,37.7 72.05,33.8 cw(c71.9,33.8) 71.9,33.65
DH2 on BOTTOM "BOTTOM119" (solid, pour order 29): 23 vertices, not listed, extent 68.55,40.5 70.477,44.745
CSN1 on BOTTOM "BOTTOM120" (solid, pour order 30): 58.013,45.204 cw(c58.013,45.254) 57.978,45.219 57.7,45.497 cw(c57.735,45.532) 57.685,45.532 57.685,49.565 cw(c57.735,49.565) 57.7,49.6 58.085,49.985 cw(c58.121,49.95) 58.121,50 60.9,50 cw(c60.9,49.85) 61.05,49.85 61.05,45.859 cw(c60.9,45.859) 61.006,45.753 60.472,45.219 cw(c60.437,45.254) 60.437,45.204
DH1 on BOTTOM "BOTTOM121" (solid, pour order 31): 34 vertices, not listed, extent 65.951,39.637 68.6,49.365
LX1 on BOTTOM "BOTTOM122" (solid, pour order 32): 22 vertices, not listed, extent 62.85,43.035 67.15,46.75
DL2 on BOTTOM "BOTTOM123" (solid, pour order 33): 33 vertices, not listed, extent 70.791,40.75 71.81,47.617
LX2 on BOTTOM "BOTTOM124" (solid, pour order 34): 75.857,46.95 cw(c75.857,47) 75.822,46.965 75.418,47.369 cw(c75.453,47.404) 75.403,47.404 75.403,51.15 cw(c75.553,51.15) 75.553,51.3 78.681,51.3 cw(c78.681,51.15) 78.831,51.15 78.831,47.37 cw(c78.781,47.37) 78.816,47.334 78.447,46.965 cw(c78.411,47) 78.411,46.95
SIG434 on BOTTOM "BOTTOM125" (solid, pour order 35): 68.506,45.747 cw(c68.506,45.797) 68.456,45.797 68.456,47.206 cw(c68.506,47.206) 68.47,47.241 68.665,47.435 cw(c68.7,47.4) 68.7,47.45 69.11,47.45 cw(c69.11,47.4) 69.159,47.4 69.159,46.93 cw(c69.11,46.93) 69.145,46.895 68.858,46.608 68.858,45.797 cw(c68.808,45.797) 68.808,45.747
BIAS on BOTTOM "BOTTOM126" (solid, pour order 36): 35 vertices, not listed, extent 69.423,37.951 78.6,39.95
SIG426 on BOTTOM "BOTTOM127" (solid, pour order 37): 17 vertices, not listed, extent 46.75,42.35 49.95,46.6
SIG450 on BOTTOM "BOTTOM128" (solid, pour order 38): 17 vertices, not listed, extent 47.75,46.9 49.15,48.25
SIG450 on BOTTOM "BOTTOM129" (solid, pour order 39): 20 vertices, not listed, extent 46.75,39.1 52.35,44
SIG449 on BOTTOM "BOTTOM130" (solid, pour order 40): 25 vertices, not listed, extent 48.6,40.45 52,42.9
SIG450 on BOTTOM "BOTTOM131" (solid, pour order 41): 19 vertices, not listed, extent 50.6,39.25 52.4,41
SIG446 on BOTTOM "BOTTOM132" (solid, pour order 42): 52,37.35 cw(c52,37.4) 51.95,37.4 51.95,37.95 51.815,38.085 cw(c51.85,38.121) 51.8,38.121 51.8,38.65 cw(c51.85,38.65) 51.85,38.7 52.35,38.7 cw(c52.35,38.65) 52.4,38.65 52.4,38.071 cw(c52.35,38.071) 52.385,38.035 52.3,37.95 52.3,37.4 cw(c52.25,37.4) 52.25,37.35
CSP1 on BOTTOM "BOTTOM133" (solid, pour order 43): 49.9,43.75 cw(c49.9,43.8) 49.85,43.8 49.85,49.679 cw(c49.9,49.679) 49.865,49.715 50.485,50.335 cw(c50.521,50.3) 50.521,50.35 57.106,50.35 cw(c57.106,50.2) 57.256,50.2 57.256,46.018 cw(c57.106,46.018) 57.212,45.912 55.065,43.765 cw(c55.029,43.8) 55.029,43.75
VIN2 on BOTTOM "BOTTOM134" (solid, pour order 44): 31 vertices, not listed, extent 40.726,26.7 51,46.1
no net on Top Solder "TOPSOLDER135" (solid, pour order 0): 21.5,56.5 ccw(c23.5,56.5) 25.5,56.5 ccw(c23.5,56.5)
no net on Top Solder "TOPSOLDER136" (solid, pour order 0): 21.5,23.5 ccw(c23.5,23.5) 25.5,23.5 ccw(c23.5,23.5)
no net on Top Solder "TOPSOLDER137" (solid, pour order 0): 104.5,23.5 ccw(c106.5,23.5) 108.5,23.5 ccw(c106.5,23.5)
no net on Top Solder "TOPSOLDER138" (solid, pour order 0): 104.5,56.5 ccw(c106.5,56.5) 108.5,56.5 ccw(c106.5,56.5)
no net on Top Paste "TOPPASTE139" (solid, pour order 0): 67.9,36 cw(c68.05,36) 68.05,36.15 71.85,36.15 cw(c71.85,36) 72,36 72,35.4 cw(c71.85,35.4) 71.85,35.25 68.05,35.25 cw(c68.05,35.4) 67.9,35.4
no net on Top Paste "TOPPASTE140" (solid, pour order 0): 70.3,33.85 cw(c70.15,33.85) 70.15,33.7 69.7,33.7 cw(c69.7,33.85) 69.55,33.85 69.55,37.65 cw(c69.7,37.65) 69.7,37.8 70.15,37.8 cw(c70.15,37.65) 70.3,37.65
no net on Bottom Solder "BOTTOMSOLDER141" (solid, pour order 0): 104.5,56.5 ccw(c106.5,56.5) 108.5,56.5 ccw(c106.5,56.5)
no net on Bottom Solder "BOTTOMSOLDER142" (solid, pour order 0): 104.5,23.5 ccw(c106.5,23.5) 108.5,23.5 ccw(c106.5,23.5)
no net on Bottom Solder "BOTTOMSOLDER143" (solid, pour order 0): 21.5,56.5 ccw(c23.5,56.5) 25.5,56.5 ccw(c23.5,56.5)
no net on Bottom Solder "BOTTOMSOLDER144" (solid, pour order 0): 21.5,23.5 ccw(c23.5,23.5) 25.5,23.5 ccw(c23.5,23.5)
no net on Top Overlay "TOPOVERLAY145" (solid, pour order 0): 48.3,35.7 cw(c48.5,35.7) 48.5,35.9 52.4,35.9 cw(c52.4,35.7) 52.6,35.7 52.6,33.4 cw(c52.4,33.4) 52.4,33.2 48.5,33.2 cw(c48.5,33.4) 48.3,33.4
no net on Top Overlay "TOPOVERLAY146" (solid, pour order 0): 75.725,45.725 76.375,46.075 76.375,45.425
no net on Top Overlay "TOPOVERLAY147" (solid, pour order 0): 36.997,57.274 cw(c37.003,57.272) 37.003,57.279 37.065,57.28 37.155,57.282 37.317,57.282 37.634,57.282 37.634,55.032 36.997,55.035 36.995,56.151 36.995,56.579 36.995,56.941 36.995,57.267 cw(c37.015,57.267) 36.997,57.274
no net on Top Overlay "TOPOVERLAY148" (solid, pour order 0): 27.328,57.282 29.338,57.282 29.338,56.72 28.672,56.72 28.669,55.035 28,55.032 28,56.72 27.328,56.72
no net on Top Overlay "TOPOVERLAY149" (solid, pour order 0): 127 vertices, not listed, extent 32.054,54.997 34.013,57.318
no net on Top Overlay "TOPOVERLAY150" (solid, pour order 0): 32 vertices, not listed, extent 40.302,55.032 42.598,57.282
no net on Top Overlay "TOPOVERLAY151" (solid, pour order 0): 34.433,57.282 35.067,57.282 35.067,56.461 35.804,56.461 35.804,57.282 36.437,57.282 36.437,55.032 35.804,55.032 35.804,55.898 35.067,55.898 35.067,55.032 34.433,55.032
no net on Top Overlay "TOPOVERLAY152" (solid, pour order 0): 55 vertices, not listed, extent 38.197,55.035 40.132,57.281
no net on Top Overlay "TOPOVERLAY153" (solid, pour order 0): 45 vertices, not listed, extent 29.558,54.995 31.685,57.318
no net on Top Overlay "TOPOVERLAY154" (solid, pour order 0): 80.275,48.075 80.925,48.425 80.925,47.881 ccw(c81.25,47.8) 80.916,47.779
no net on Top Overlay "TOPOVERLAY155" (solid, pour order 0): 63.65,40.65 63.95,41.3 64.3,40.65 63.99,40.65 ccw(c63.9,40.25) 63.81,40.65
no net on Top Overlay "TOPOVERLAY156" (solid, pour order 0): 62.181,45.125 ccw(c62.1,44.8) 62.079,45.134 62.375,45.775 62.725,45.125

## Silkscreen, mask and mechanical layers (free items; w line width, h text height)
Top Overlay:
  lines w0.2: 58.5,37 60.9,37 60.9,36.845 60.9,37.7 61.5,38.3 61.5,40.6 ; 60.9,36.9 60.9,37.2 ; 61.3,36.717 61.3,37 64,37 ; 64,36.8 64,37 ; 64.069,37.969 64,37.9 64,37 ; 64.381,38.281 65.5,39.4 65.5,39.9 65.9,40.3 ; 64.6,40.7 64.6,40.3 67.042,40.3 ; 65.4,29.6 66.7,29.6 67.1,30 67.1,30.7 67.216,30.816 ; 65.4,30.7 65.7,30.7 66,31 66.9,31.9 68.8,31.9 69.1,31.6 69.3,31.6 ; 67.558,40.3 68.2,40.3 69,41.1 ; 67.606,31 68.6,31 ; 72.8,25.5 72.8,25.8 72.9,25.9 ; 72.9,28.1 72.9,25.9 ; 76.41,24.49 75.7,25.2 75.7,25.9 72.9,25.9 ; 76.45,41.15 76.9,40.7 76.9,39.05 77.05,39.05 ; 76.489,24.411 76.5,24.4 ; 76.9,38.75 76.9,39.1 ; 76.9,54.65 76.9,54.2 77.25,53.85 79.6,53.85 79.737,53.713 ; 77.1,39.05 78.1,39.05 ; 78.25,36.95 78.1,37.1 78.1,40.75 78.5,41.15 78.75,41.15 79.1,41.5 79.1,41.75 79.3,41.95 79.418,41.95 ; 79.907,53.543 79.95,53.5 80.5,53.5 80.75,53.25 80.843,53.157 ; 80.1,46.5 80.1,46 80.5,45.6 81.05,45.6 ; 81.096,52.604 81.3,52.4 85.75,52.4 ; 81.421,45.6 81.979,45.6 ; 82.321,45.6 82.879,45.6 ; 83.221,45.6 83.779,45.6 ; 84.121,45.6 84.679,45.6 ; 84.4,45.7 84.4,46.1 ; 84.4,46 84.4,52.3 ; 85.021,45.6 85.579,45.6 ; 85.921,45.6 86.479,45.6 ; 86.821,45.6 87.379,45.6 ; 87.721,45.6 88.6,45.6 ; 89.735,22.315 90.1,21.95
  text "OUTPUT" at 99.8,52.45 h0.71
  text "INPUT" at 21.05,51.3 h0.8
  text "BUCK-BOOST" at 40.2,36.1 h0.89
  text "TYPE1" at 40.2,34.45 h0.71
  text "CONTROL" at 61.163,24.308 h0.8
  text "INPUT" at 61.151,22.898 h0.8
Bottom Overlay:
  lines w0.2: 53.55,33.55 54.179,33.55 ; 54.521,33.55 55.079,33.55 ; 55.421,33.55 55.979,33.55 ; 56.321,33.55 56.6,33.55 56.6,32.2 ; 59.2,51.75 61.3,51.75 62.25,50.8 ; 62.25,49.86 62.25,48.7 62.25,48.6 62.284,48.566 ; 62.25,50.34 62.25,50.8 ; 62.485,48.365 63.6,47.25 63.6,46.9 ; 62.5,43 63.15,43 ; 62.6,49.95 62.95,50.3 66.65,50.3 66.65,55.1 66.2,55.55 65.6,55.55 ; 63.351,43 65.7,43 65.85,42.85 66.7,42.85 66.9,42.65 ; 63.6,43.871 63.6,43.979 ; 63.6,44.721 63.6,44.829 ; 63.6,45.571 63.6,45.679 ; 63.6,46.421 63.6,47 ; 64.8,54.1 65.6,54.1 65.6,57 64.8,57 ; 65.6,51.3 65.6,50.8 62.25,50.8 ; 66.65,50.25 67.2,50.25 67.4,50.05 67.4,47.15 66.95,46.7 ; 67.85,45.35 67.85,47.25 68.45,47.85 69.8,47.85 ; 68,53 68,52.2 69.8,52.2 ; 69.85,47.85 69.85,52.2 71.1,52.2 71.1,53 ; 69.85,47.95 70.1,47.7 ; 70.226,47.573 70.25,47.55 70.25,47.507 ; 70.25,46.25 70.25,46.775 ; 70.75,45.25 70.858,45.142 ; 70.8,48.1 73.4,48.1 73.55,48.1 74.35,47.3 74.4,47.25 74.45,47.2 74.45,47 ; 70.85,45.2 71.8,45.2 ; 72.001,45.2 72.35,45.2 72.45,45.1 ; 72.1,53 72.1,52.2 75.3,52.2 75.3,52.7 75.3,53 ; 73.7,48.05 73.7,49.85 ; 73.7,49.8 73.7,52.2 ; 75.1,30.929 75.1,26.8 78.8,26.8 ; 75.1,31.271 75.1,31.7 ; 75.135,31.1 77.4,31.1 77.4,32.1 ; 77.8,33.6 77.8,33.2 ; 77.8,39.3 77.8,39.7 81.7,39.7 81.7,39.2 81.7,38.3 81.1,38.3 ; 78.8,28.1 77.8,28.1 77.8,33.2 ; 80,38.3 81,38.3 ; 81.7,33.8 81.7,33.2 77.8,33.2 ; 81.7,39.5 81.7,39.9 ; 81.7,39.8 81.7,40.6 ; 82.2,34.7 81.8,35.1 ; 82.2,35.5 81.8,35.1 ; 83,35.1 81.8,35.1 ; 84,29.9 83.1,29.9 83.1,39.3 83.8,39.3 91,39.3
  text "ADDR SELECT" at 86.4,40.7 h0.43
  text "CURRENT COMP" at 85.885,27.3 h0.43
  text "VOLTAGE COMP" at 85.885,26.1 h0.43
